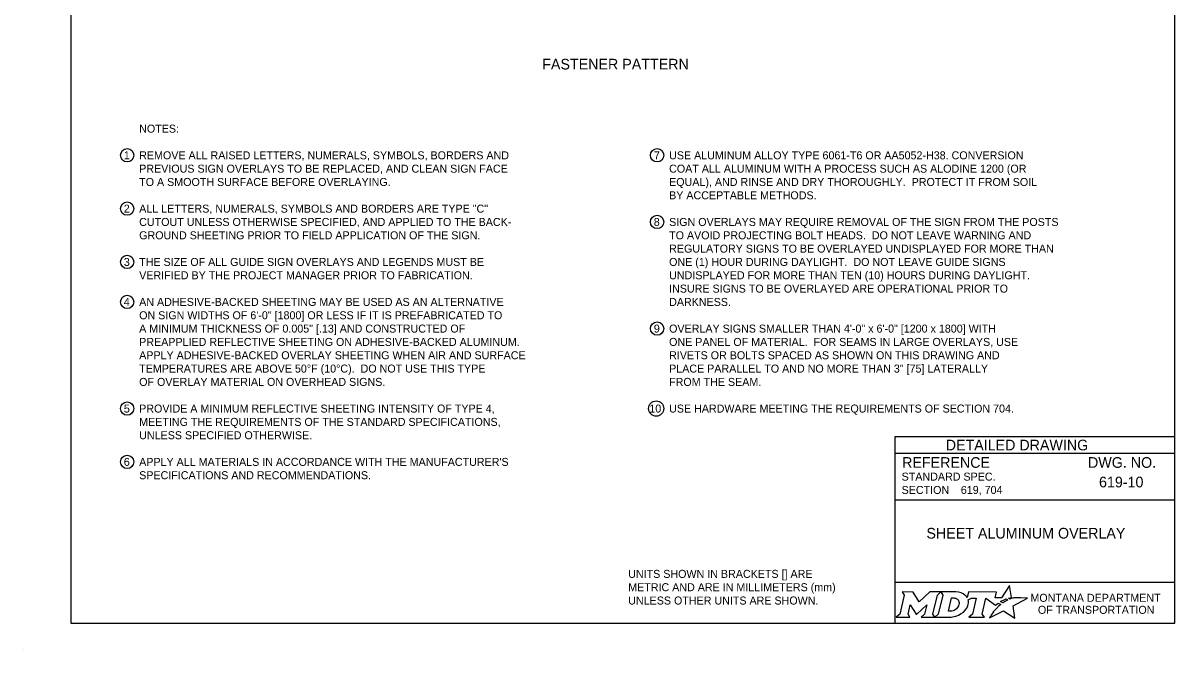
# Model space of a CAD drawing. Extents: x 49991.4 to 50021, y 49987.6 to 50011.4.
# Drawn here: x 49999.98 to 50008.61, y 49999.86 to 50004.57 of the extents above; entities that cross this region are included whole.
import ezdxf

# ---------------------------------------------------------------- set-up
doc = ezdxf.new("R2010")
doc.units = 0
doc.layers.add('Level 1', color=7, linetype='Continuous')
doc.layers.add('Level 2', color=7, linetype='Continuous')

msp = doc.modelspace()

# ---------------------------------------------------------------- linework, layer by layer
at = {"layer": 'Level 1'}
msp.add_line((49999.9766, 49999.8624), (49999.9766, 49999.8624), dxfattribs=at)
msp.add_lwpolyline([(50008.6146, 50011.2628), (50000.3356, 50011.2628), (50000.3356, 50000.0624), (50008.6146, 50000.0624)], close=True, dxfattribs=at)
at = {"layer": 'Level 2'}
for p, q in [((50008.6146, 50001.4624), (50006.5146, 50001.4624)), ((50006.5146, 50001.4624), (50006.5146, 50000.0624)), ((50008.6146, 50001.3374), (50006.5146, 50001.3374)), ((50008.2507, 50001.1223), (50008.2507, 50001.1223)), ((50008.6146, 50000.9874), (50006.5146, 50000.9874)), ((50007.0089, 50001.0629), (50007.0089, 50001.0629)), ((50007.5646, 50000.7383), (50007.5646, 50000.7383)), ((50008.6146, 50000.3693), (50006.5146, 50000.3693))]:
    msp.add_line(p, q, dxfattribs=at)
for points in [[(50006.5701, 50000.2974), (50006.5842, 50000.274), (50006.5507, 50000.1307), (50006.525, 50000.1082), (50006.6266, 50000.1082), (50006.6131, 50000.131), (50006.6293, 50000.2011), (50006.673, 50000.1321), (50006.6783, 50000.1321), (50006.7534, 50000.2016), (50006.737, 50000.1305), (50006.7123, 50000.1085), (50006.8139, 50000.1085), (50006.8001, 50000.1318), (50006.8333, 50000.2742)], [(50006.8333, 50000.2742), (50006.8586, 50000.2974), (50006.7762, 50000.2974), (50006.6966, 50000.2244), (50006.6521, 50000.2971), (50006.5701, 50000.2974)], [(50006.9722, 50000.2974), (50006.8586, 50000.2974), (50006.8733, 50000.2745), (50006.8394, 50000.1307), (50006.8139, 50000.1085), (50006.9245, 50000.1085)], [(50007.3771, 50000.2447), (50007.3668, 50000.2503), (50007.3784, 50000.2531), (50007.39, 50000.2551), (50007.3726, 50000.3452), (50007.3131, 50000.2539), (50007.2658, 50000.2532), (50007.2761, 50000.2973), (50007.0669, 50000.2974), (50007.0568, 50000.2549), (50007.051, 50000.2632)], [(50006.9962, 50000.2107), (50006.995, 50000.2026), (50006.9918, 50000.1933), (50006.9876, 50000.1851), (50006.982, 50000.1776), (50006.9755, 50000.1707), (50006.9676, 50000.1644), (50006.9593, 50000.1597), (50006.9502, 50000.1558), (50006.9411, 50000.1535), (50006.9319, 50000.1526), (50006.916, 50000.1526), (50006.9396, 50000.2526), (50006.9556, 50000.2526), (50006.9632, 50000.252), (50006.9708, 50000.2501), (50006.9774, 50000.2471), (50006.9835, 50000.2429), (50006.9883, 50000.2379), (50006.992, 50000.2319), (50006.9947, 50000.2257), (50006.9963, 50000.2183), (50006.9963, 50000.2153), (50006.9962, 50000.2107)], [(50007.0636, 50000.2383), (50007.0882, 50000.2514), (50007.1251, 50000.2514), (50007.0965, 50000.1309), (50007.069, 50000.1082), (50007.1852, 50000.1082), (50007.1682, 50000.1311), (50007.1964, 50000.2513), (50007.2677, 50000.1996), (50007.2888, 50000.2147), (50007.3085, 50000.2038)], [(50007.2527, 50000.1479), (50007.2374, 50000.1235), (50007.2327, 50000.116), (50007.2269, 50000.1074), (50007.2246, 50000.1031), (50007.3299, 50000.1562), (50007.4138, 50000.1011), (50007.4007, 50000.1938), (50007.5076, 50000.2522), (50007.4583, 50000.253), (50007.4282, 50000.2534), (50007.4074, 50000.2537), (50007.4006, 50000.2522), (50007.3957, 50000.251), (50007.3873, 50000.2487), (50007.3771, 50000.2447)], [(50007.3267, 50000.2171), (50007.3243, 50000.2154), (50007.306, 50000.225), (50007.3163, 50000.2307), (50007.3204, 50000.2329), (50007.329, 50000.2369), (50007.3347, 50000.2395), (50007.3426, 50000.2425), (50007.3499, 50000.2452), (50007.3617, 50000.2378), (50007.3577, 50000.2357), (50007.3531, 50000.2332), (50007.3489, 50000.231), (50007.3439, 50000.2281), (50007.342, 50000.227), (50007.3393, 50000.2254), (50007.3368, 50000.224), (50007.3345, 50000.2224), (50007.3319, 50000.2206), (50007.3292, 50000.2188), (50007.3267, 50000.2171)], [(50006.9702, 50000.1158), (50006.9786, 50000.1184), (50006.9916, 50000.1238), (50007.012, 50000.1348)], [(50007.2666, 50000.164), (50007.2666, 50000.164)]]:
    msp.add_lwpolyline(points, dxfattribs=at)
for centre, radius in [((50000.7575, 50003.5735), 0.05), ((50004.7314, 50003.5735), 0.05), ((50000.7575, 50003.1735), 0.05), ((50004.7314, 50003.0735), 0.05), ((50000.7575, 50002.7735), 0.05), ((50000.7575, 50002.4735), 0.05), ((50004.7314, 50002.2735), 0.05), ((50000.7575, 50001.6735), 0.05), ((50004.7245, 50001.6735), 0.0569), ((50000.7575, 50001.2735), 0.05)]:
    msp.add_circle(centre, radius, dxfattribs=at)
for centre, radius, start, end in [((50006.9953, 50000.219), 0.0709, 339.53292, 15.85821), ((50006.9513, 50000.2363), 0.1183, 300.91025, 339.13831)]:
    msp.add_arc(centre, radius, start, end, dxfattribs=at)
for centre, major_axis, ratio, start_param, end_param in [((50006.9701, 50000.25), (0.0834, -0.0037), 0.568097, 0.61298, 1.570796), ((50007.0257, 50000.2573), (0.0361, -0.0295), 0.469099, 1.225588, 1.570796), ((50007.2974, 50000.1941), (-0.0112, -0.0097), 0.021651, 3.157348, 6.283185), ((50006.9248, 50000.2568), (0, 0.1484), 0.987302, 3.139398, 3.456847), ((50007.2597, 50000.1559), (-0.00694, -0.00806), 0.008222, 0, 3.137361), ((50007.2764, 50000.1742), (-0.0098, -0.0102), 0.016458, 3.141593, 6.279097)]:
    msp.add_ellipse(centre, major_axis=major_axis, ratio=ratio, start_param=start_param, end_param=end_param, dxfattribs=at)

# ---------------------------------------------------------------- texts
for s, height, p in [('FASTENER PATTERN', 0.08, (50003.8697, 50004.2174)), ('NOTES:', 0.06, (50000.8475, 50003.7435)), ('1', 0.06, (50000.7323, 50003.5435)), ('REMOVE ALL RAISED LETTERS, NUMERALS, SYMBOLS, BORDERS AND', 0.06, (50000.8475, 50003.5435)), ('7', 0.06, (50004.7076, 50003.5435)), ('USE ALUMINUM ALLOY TYPE 6061-T6 OR AA5052-H38. CONVERSION', 0.06, (50004.8214, 50003.5435)), ('PREVIOUS SIGN OVERLAYS TO BE REPLACED, AND CLEAN SIGN FACE', 0.06, (50000.8475, 50003.4435)), ('COAT ALL ALUMINUM WITH A PROCESS SUCH AS ALODINE 1200 (OR', 0.06, (50004.8214, 50003.4435)), ('TO A SMOOTH SURFACE BEFORE OVERLAYING.', 0.06, (50000.8475, 50003.3435)), ('EQUAL), AND RINSE AND DRY THOROUGHLY.  PROTECT IT FROM SOIL', 0.06, (50004.8214, 50003.3435)), ('BY ACCEPTABLE METHODS.', 0.06, (50004.8214, 50003.2435)), ('2', 0.06, (50000.7323, 50003.1435)), ('ALL LETTERS, NUMERALS, SYMBOLS AND BORDERS ARE TYPE "C"', 0.06, (50000.8475, 50003.1435)), ('CUTOUT UNLESS OTHERWISE SPECIFIED, AND APPLIED TO THE BACK-', 0.06, (50000.8475, 50003.0435)), ('8', 0.06, (50004.7064, 50003.0435)), ('SIGN OVERLAYS MAY REQUIRE REMOVAL OF THE SIGN FROM THE POSTS', 0.06, (50004.8214, 50003.0435)), ('GROUND SHEETING PRIOR TO FIELD APPLICATION OF THE SIGN.', 0.06, (50000.8475, 50002.9435)), ('TO AVOID PROJECTING BOLT HEADS.  DO NOT LEAVE WARNING AND', 0.06, (50004.8214, 50002.9435)), ('REGULATORY SIGNS TO BE OVERLAYED UNDISPLAYED FOR MORE THAN', 0.06, (50004.8214, 50002.8435)), ('3', 0.06, (50000.7323, 50002.7435)), ('THE SIZE OF ALL GUIDE SIGN OVERLAYS AND LEGENDS MUST BE', 0.06, (50000.8475, 50002.7435)), ('ONE (1) HOUR DURING DAYLIGHT.  DO NOT LEAVE GUIDE SIGNS', 0.06, (50004.8214, 50002.7435)), ('VERIFIED BY THE PROJECT MANAGER PRIOR TO FABRICATION.', 0.06, (50000.8475, 50002.6435)), ('UNDISPLAYED FOR MORE THAN TEN (10) HOURS DURING DAYLIGHT.', 0.06, (50004.8214, 50002.6435)), ('INSURE SIGNS TO BE OVERLAYED ARE OPERATIONAL PRIOR TO', 0.06, (50004.8214, 50002.5435)), ('4', 0.06, (50000.7323, 50002.4435)), ('AN ADHESIVE-BACKED SHEETING MAY BE USED AS AN ALTERNATIVE', 0.06, (50000.8475, 50002.4435)), ('DARKNESS.', 0.06, (50004.8214, 50002.4435)), ('ON SIGN WIDTHS OF 6\'-0" [1800] OR LESS IF IT IS PREFABRICATED TO', 0.06, (50000.8475, 50002.3435)), ('A MINIMUM THICKNESS OF 0.005" [.13] AND CONSTRUCTED OF ', 0.06, (50000.8475, 50002.2435)), ('9', 0.06, (50004.7069, 50002.2435)), ('OVERLAY SIGNS SMALLER THAN 4\'-0" x 6\'-0" [1200 x 1800] WITH ', 0.06, (50004.8214, 50002.2435)), ('PREAPPLIED REFLECTIVE SHEETING ON ADHESIVE-BACKED ALUMINUM.  ', 0.06, (50000.8475, 50002.1435)), ('ONE PANEL OF MATERIAL.  FOR SEAMS IN LARGE OVERLAYS, USE', 0.06, (50004.8214, 50002.1435)), ('APPLY ADHESIVE-BACKED OVERLAY SHEETING WHEN AIR AND SURFACE', 0.06, (50000.8475, 50002.0435)), ('RIVETS OR BOLTS SPACED AS SHOWN ON THIS DRAWING AND', 0.06, (50004.8214, 50002.0435)), ('TEMPERATURES ARE ABOVE 50°F (10°C).  DO NOT USE THIS TYPE ', 0.06, (50000.8475, 50001.9435)), ('PLACE PARALLEL TO AND NO MORE THAN 3" [75] LATERALLY ', 0.06, (50004.8214, 50001.9435)), ('OF OVERLAY MATERIAL ON OVERHEAD SIGNS.', 0.06, (50000.8475, 50001.8435)), ('FROM THE SEAM.', 0.06, (50004.8214, 50001.8435)), ('5', 0.06, (50000.7323, 50001.6435)), ('PROVIDE A MINIMUM REFLECTIVE SHEETING INTENSITY OF TYPE 4,', 0.06, (50000.8475, 50001.6435)), ('10', 0.06, (50004.673, 50001.6435)), ('USE HARDWARE MEETING THE REQUIREMENTS OF SECTION 704.', 0.06, (50004.8214, 50001.6435)), ('MEETING THE REQUIREMENTS OF THE STANDARD SPECIFICATIONS,', 0.06, (50000.8475, 50001.5435)), ('UNLESS SPECIFIED OTHERWISE.', 0.06, (50000.8475, 50001.4435)), ('DETAILED DRAWING', 0.0799, (50006.8956, 50001.3599)), ('6', 0.06, (50000.7323, 50001.2435)), ("APPLY ALL MATERIALS IN ACCORDANCE WITH THE MANUFACTURER'S", 0.06, (50000.8475, 50001.2435)), ('REFERENCE', 0.08, (50006.5682, 50001.229)), ('DWG. NO.', 0.08, (50007.9624, 50001.229)), ('SPECIFICATIONS AND RECOMMENDATIONS.', 0.06, (50000.8475, 50001.1435)), ('STANDARD SPEC.', 0.06, (50006.5649, 50001.133)), ('619-10', 0.08, (50008.0451, 50001.0823)), ('SECTION', 0.06, (50006.5649, 50001.033)), ('619, 704', 0.06, (50007.0089, 50001.0329)), ('SHEET ALUMINUM OVERLAY', 0.08, (50006.7508, 50000.6983)), ('UNITS SHOWN IN BRACKETS [] ARE ', 0.06, (50004.5146, 50000.4033)), ('METRIC AND ARE IN MILLIMETERS (mm) ', 0.06, (50004.5146, 50000.3033)), ('UNLESS OTHER UNITS ARE SHOWN.', 0.06, (50004.5146, 50000.2033)), ('MONTANA DEPARTMENT', 0.06, (50007.5308, 50000.2236)), ('OF TRANSPORTATION', 0.06, (50007.587, 50000.1336))]:
    msp.add_text(s, height=height, dxfattribs=at).set_placement(p)

doc.saveas('drawing.dxf')
